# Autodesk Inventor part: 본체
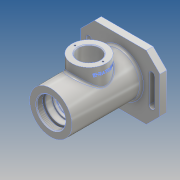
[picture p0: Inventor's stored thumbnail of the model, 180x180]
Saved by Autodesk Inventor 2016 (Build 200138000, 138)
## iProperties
Created: 2017-10
Part Number: 본체
Material: 알루미늄 6061
Document SubType Name: Modeling
Designer: Administrator
Density: 2.7 g/cm^3
Appearance: 알루미늄 - 평지
Mass: 735.362 g
Surface Area: 649.997 cm^2
Volume: 272.356 cm^3
Author: Administrator
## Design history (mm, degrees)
sketch "스케치1"
  geometry: L1 (0, 0)-(115, 0); L2 (0, 0)-(0, 31); L3 (0, 31)-(115, 31); L4 (115, 31)-(115, 0); L5 (0, 21)-(9, 21); L6 (9, 21)-(9, 24); L7 (9, 24)-(12, 24); L8 (12, 24)-(12, 20); L9 (12, 20)-(21, 20); L10 (21, 20)-(21, 17.5); L11 (21, 17.5)-(24.25, 17.5); L12 (24.25, 17.5)-(24.25, 18.5); L13 (24.25, 18.5)-(26, 18.5); L14 (26, 18.5)-(26, 17.5); L15 (26, 17.5)-(37, 17.5); L16 (37, 17.5)-(37, 26); L17 (37, 26)-(75, 26); L18 (75, 26)-(75, 17.5); L19 (75, 17.5)-(85.7, 17.5); L20 (91, 10)-(93.7, 10); L21 (93.7, 10)-(93.7, 12.2); L22 (94, 12.5)-(100.3, 12.5); L23 (86, 17.2)-(86, 16.5); L24 (86, 16.5)-(91, 16.5); L25 (91, 16.5)-(91, 10); L26 (101, 12.904)-(101, 14.022); L27 (102.818, 16.779)-(115, 22); L28 (100.3, 12.5)-(101, 12.904); A1 r 0.3 centre (94, 12.2) between (94, 12.5) and (93.7, 12.2); A2 r 0.3 centre (85.7, 17.2) between (86, 17.2) and (85.7, 17.5); A3 r 3 centre (104, 14.022) between (102.818, 16.779) and (101, 14.022); 4 further points
  constraints: 56 end point, 19 perpendicular, 12 point on line, 6 point on circle, 6 tangent, 3 centre point, 3 vertical, 2 horizontal
  dimensions: "d1" = 115 distance of L2.end L3.end; "d2" = 62 diameter of L3 L1; "d3" = 42 diameter of L5 L1; "d4" = 48 diameter of L7 L1; "d5" = 40 diameter of L9 L1; "d6" = 35 diameter of L11 L1; "d7" = 37 diameter of L13 L1; "d8" = 52 diameter of L17 L1; "d9" = 35 diameter of L19 L1; "d10" = 33 diameter of L24 L1; "d11" = 20 diameter of L20 L1; "d12" = 25 diameter of L22 L1; "d13" = 32 diameter of point (101, 16) L1; "d14" = 44 diameter of L27.end L1; "d15" = 3 distance of L6.end L7.end; "d16" = 12 distance between parallel lines of L2 L8; "d17" = 21 distance between parallel lines of L2 L10; "d18" = 38 distance of L16.end L17.end; "d19" = 14 distance between parallel lines of L4 L26; "d20" = 7.3 distance between parallel lines of L26 L21; "d21" = 2.7 distance of L20.start L20.end; "d22" = 5 distance between parallel lines of L23 L25; "d23" = 26 distance between parallel lines of L2 L14; "d24" = 1.75 distance of L12.end L13.end; "d25" = 11 distance of L18.end point (86, 17.5); "d67" = 0.3 radius of A1; "d68" = 0.7 distance of L22.end point (101, 12.5); "d69" = 30 deg angle of L22 L28; "d70" = 0.3 radius of A2; "d74" = 3 radius of A3
revolve "회전1" sketch "스케치1" stored, may be unused: angle "d26" = 90 deg
node "작업 평면1"
sketch "스케치2"
  geometry: L1 (38, -47)-(-38, -47); L2 (-58, -27)-(-58, 27); L3 (-38, 47)-(38, 47); L4 (58, 27)-(58, -27); L5 (38, 47)-(58, 27); L6 (-58, 27)-(-38, 47); L7 (-58, -27)-(-38, -47); L8 (38, -47)-(58, -27); L9 (42, -20)-(42, 20); L10 (50, 20)-(50, -20); L11 (0, -4.964)-(0, 10.106); L12 (-42, -20)-(-42, 20); L13 (-50, 20)-(-50, -20); C1 r 31 at (0, 0) reference; A1 r 4 centre (46, -20) between (42, -20) and (50, -20); A2 r 4 centre (46, 20) between (42, 20) and (50, 20); A3 r 4 centre (-46, -20) between (-42, -20) and (-50, -20); A4 r 4 centre (-46, 20) between (-42, 20) and (-50, 20); 11 further points
  constraints: 26 end point, 8 point on circle, 8 point on line, 8 symmetric about line, 5 horizontal alignment, 4 centre point, 4 midpoint, 2 parallel, 2 vertical, 2 vertical alignment, 1 horizontal, 1 perpendicular, 1 tangent, 2 other
  dimensions: "d28" = 116 distance between parallel lines of L4 L2; "d29" = 94 distance between parallel lines of L3 L1; "d30" = 20 distance of L3.end point (58, 47); "d31" = 20 distance of L4.start point (58, 47) (= d30); "d32" = 20 distance of L2.end point (-58, 47) (= d30); "d33" = 20 distance of L3.start point (-58, 47) (= d32); "d34" = 20 distance of L2.start point (-58, -47) (= d30); "d35" = 20 distance of L1.end point (-58, -47) (= d34); "d36" = 20 distance of L1.start point (58, -47); "d37" = 20 distance of L4.end point (58, -47) (= d36); "d38" = 8 diameter of A1; "d39" = 8 diameter of A2; "d40" = 40 distance of L10.start L10.end; "d41" = 46 horizontal distance of point (0, 0) A2.centre; "d42" = 46 horizontal distance of point (0, 0) A4.centre
extrude "돌출1" join sketch "스케치2" distance "d43" = 10; taper "d44" = 0 deg
sketch "스케치3"
  geometry: C1 r 31 at (0, 0) reference; C2 r 35 at (0, 0); C3 r 31 at (0, 0) reference
  constraints: 1 centre point, 1 coincident
  dimensions: "d45" = 70 diameter of C2
extrude "돌출2" join sketch "스케치3" distance "d46" = 3; taper "d47" = 0 deg
node "작업 평면2"
sketch "스케치4"
  geometry: C1 r 25 at (0, 56); 1 further point
  constraints: 1 centre point, 1 vertical alignment
  dimensions: "d49" = 50 diameter of C1; "d50" = 56 distance of point (0, 0) C1.centre
extrude "돌출3" join sketch "스케치4" stored distance "d51" = 3; taper "d52" = 0 deg
sketch "스케치5"
  geometry: C1 r 25 at (0, 0) reference; C2 r 16 at (0, 0); 1 further point
  constraints: 1 centre point, 1 coincident
  dimensions: "d53" = 32 diameter of C2
extrude "돌출4" cut sketch "스케치5" stored distance "d54" = 3; taper "d55" = 0 deg
sketch "스케치6"
  geometry: C1 r 16 at (0, 0) reference; 3 further points
  constraints: 2 horizontal alignment
  dimensions: "d56" = 20.5 distance of C1.centre point (-20.5, 0); "d57" = 41 distance of point (20.5, 0) point (-20.5, 0)
hole "구멍1" sketch "스케치6" at (-20.5, 0), (20.5, 0) diameter "d58" = 2.459; stored, may be unused: countersink angle "d62" = 90 deg, drill point angle "d64" = 118 deg; dims "d59" = 6, "d60" = 4, "d61" = 2, "d63" = 8
feature "스레드1" dims "d65" = 10, "d66" = 0
fillet "모깎기1" dims "d71" = 3
fillet "모깎기2" dims "d72" = 3
fillet "모깎기3" dims "d73" = 3
chamfer "모따기1" distance "d75" = 1; stored, may be unused: second distance "d76" = 2, angle "d77" = 45 deg
chamfer "모따기2" distance "d78" = 1; stored, may be unused: second distance "d79" = 2, angle "d80" = 45 deg
node "작업 평면3"
sketch "스케치7"
  geometry: L1 (-56, -78)-(-56, -16) reference; L2 (-25, 0)-(25, 0) reference; 2 further points
  constraints: 1 other
  dimensions: "d81" = 56 distance from line of L1 point (0, -10); "d82" = 10 distance from line of L2 point (0, -10)
feature "엠보싱1" sketch "스케치7" dims "d2" = 62, "d12" = 25, "d83" = 0.5, "d84" = 0
node "솔리드1"
other parameters: "d27" = -3, "d48" = 47
